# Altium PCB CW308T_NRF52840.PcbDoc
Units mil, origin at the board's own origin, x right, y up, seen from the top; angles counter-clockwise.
Board outline 2060 x 2540 mil, 2 copper layers (Top Layer, Bottom Layer); 28 components, 41 nets, 193 pads, 144 vias.
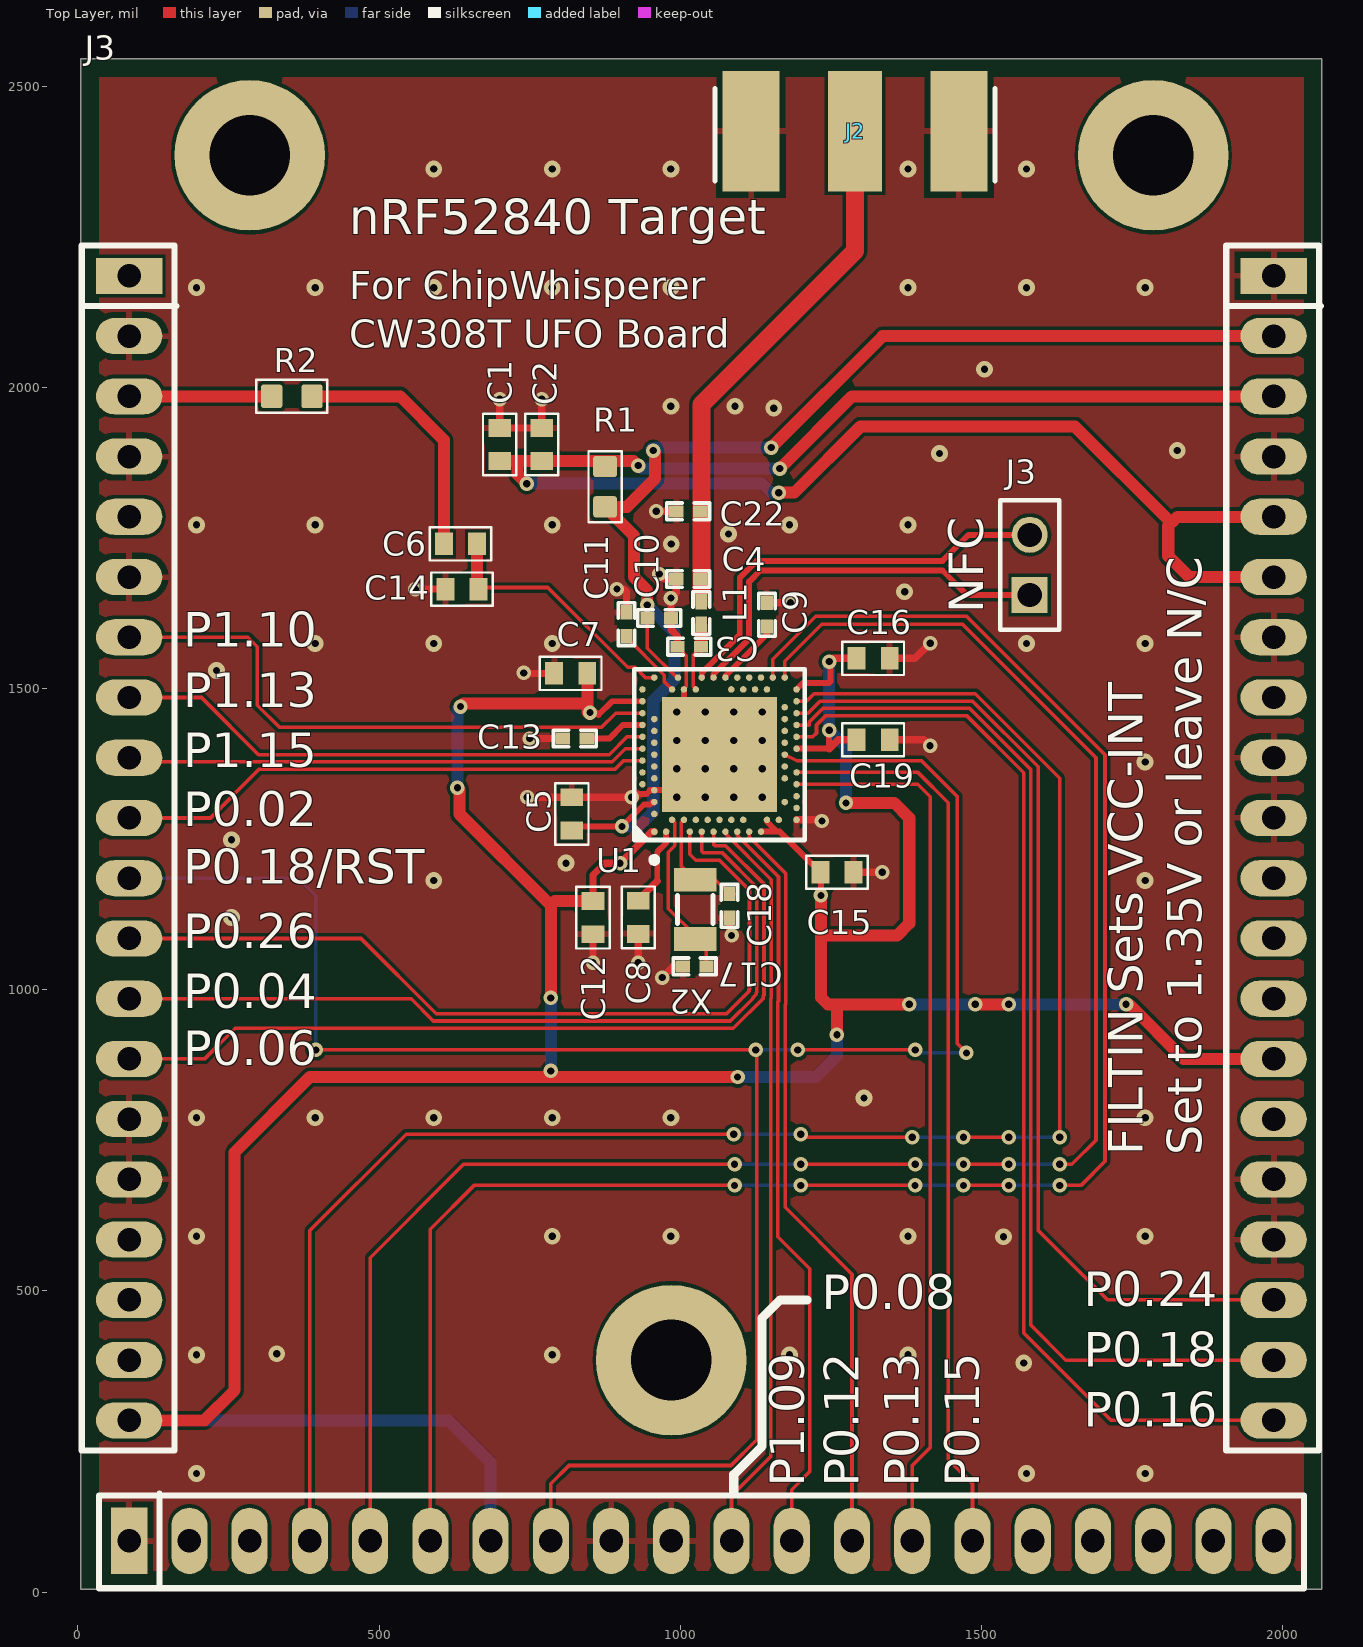
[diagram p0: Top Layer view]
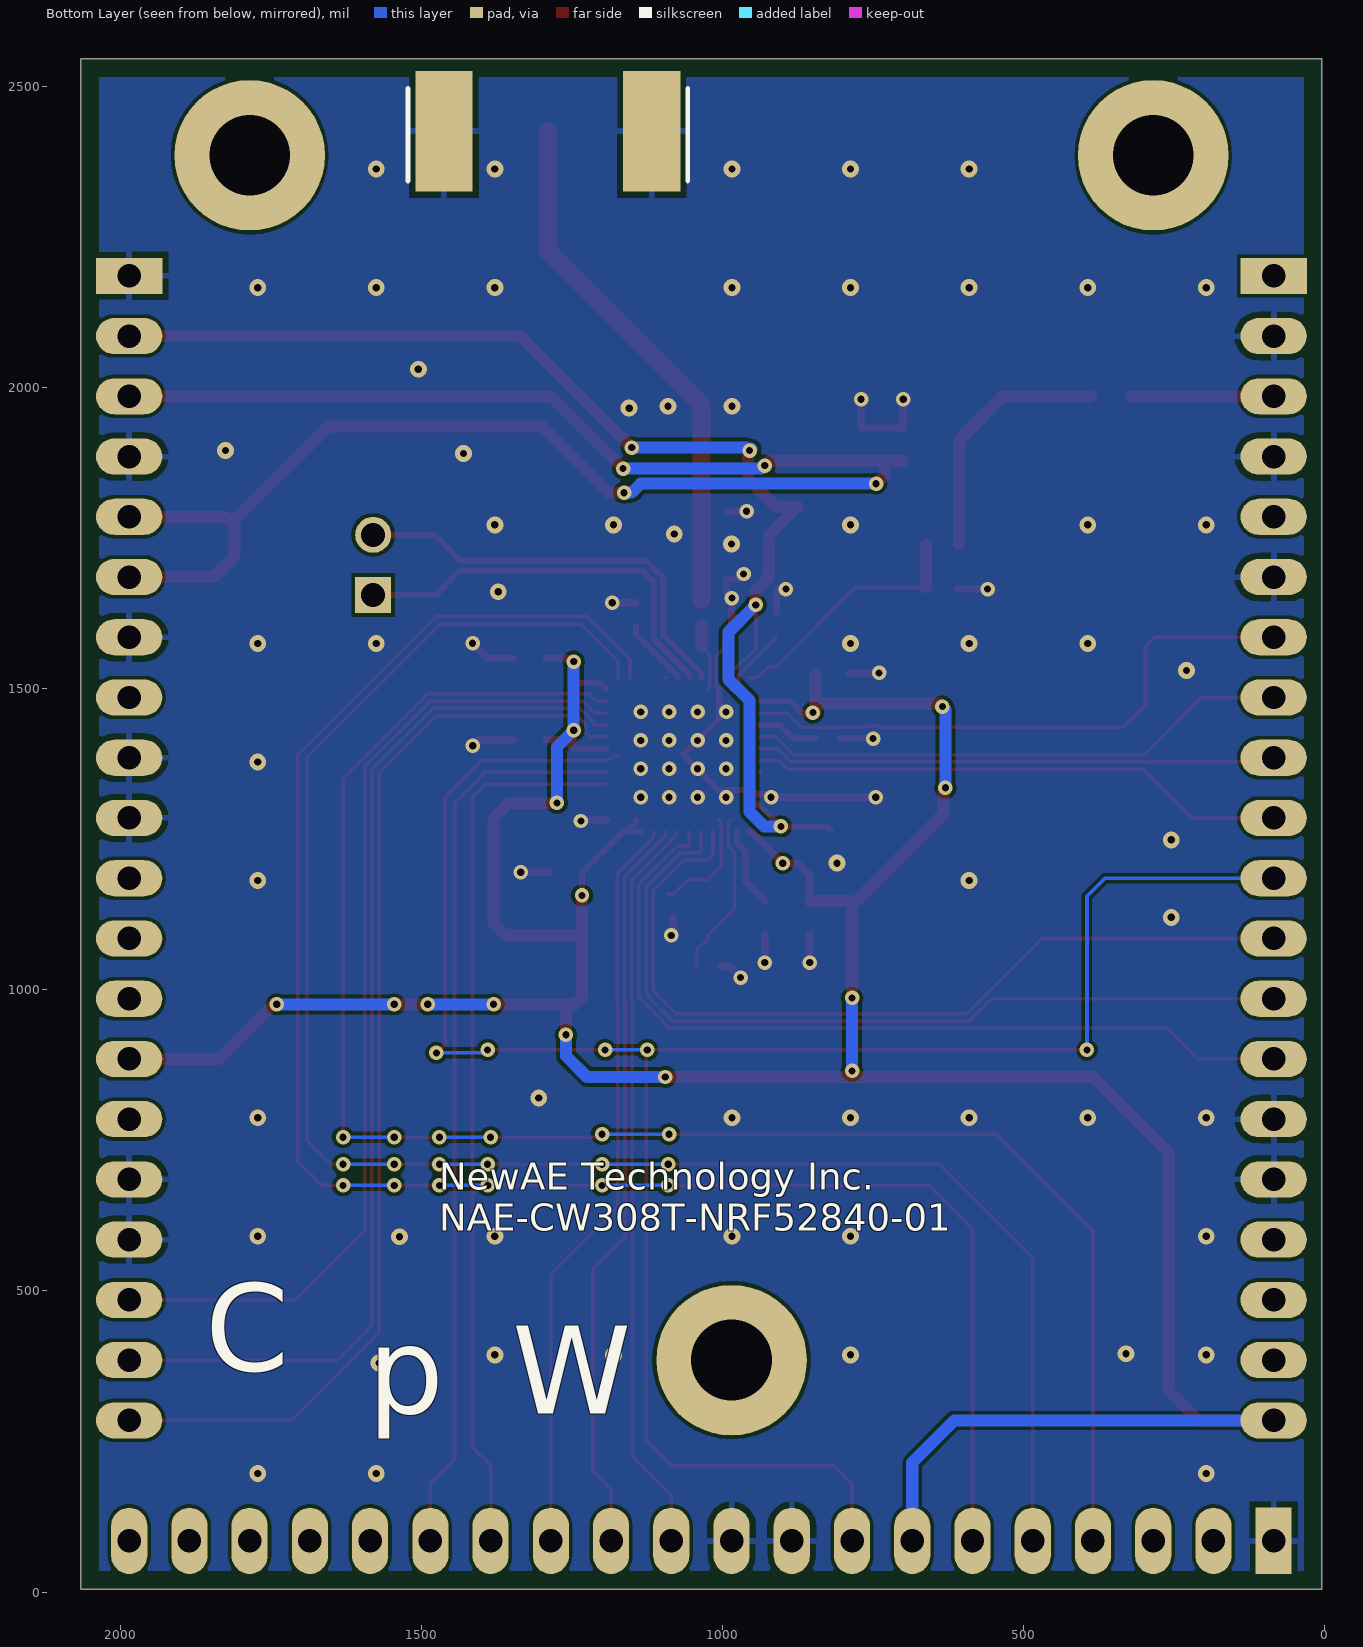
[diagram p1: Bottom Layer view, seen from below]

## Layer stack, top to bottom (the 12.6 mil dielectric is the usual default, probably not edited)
Top Solder: solder mask 0.4, Solder Resist, Dk 3.5
Top Layer: signal copper 1.4
Dielectric 1: dielectric 12.6, FR-4, Dk 4.8
Bottom Layer: signal copper 1.4
Bottom Solder: solder mask 0.4, Solder Resist, Dk 3.5

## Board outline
5,5 5,2545 2065,2545 2065,5

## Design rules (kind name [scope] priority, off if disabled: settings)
BoardOutlineClearance Silk_to_Outline [(OnLayer('Top Overlay'))] p1: gap=0 ignorepadtopadclearanceinfootprint=FALSE
BoardOutlineClearance [All] p2: gap=30 ignorepadtopadclearanceinfootprint=FALSE
Clearance [All] p1: gap=6 ignorepadtopadclearanceinfootprint=FALSE except(0: Arc-Hole Track-Hole SMDPad-Hole THPad-Hole Via-Hole Fill-Hole Poly-Hole Region-Hole Text-Hole)
HoleSize [All] p1: absolutevalues=TRUE maxlimit=200 minlimit=1 maxpercent=80.000 minpercent=20.000
MinimumSolderMaskSliver [All] p1: minsoldermaskwidth=5
PlaneConnect PlaneConnect_viaDirect [IsVia] p1: planeconnectstyle=Direct reliefexpansion=20 reliefentries=4 reliefconductorwidth=10 reliefairgap=10
PlaneConnect [All] p2: planeconnectstyle=Relief reliefexpansion=20 reliefentries=4 reliefconductorwidth=10 reliefairgap=10
PolygonConnect PolygonConnect_viaDirect [All vs isVia] p1: connectstyle=Direct reliefconductorwidth=10 reliefentries=4 polygonreliefangle="90 Angle" airgapwidth=10
PolygonConnect [All] p2: connectstyle=Relief reliefconductorwidth=10 reliefentries=4 polygonreliefangle="90 Angle" airgapwidth=10
RoutingVias [All] p1: holewidth=28 width=24 viastyle="Through Hole" minholewidth=12 minwidth=24 maxholewidth=12 maxwidth=50
SilkToSilkClearance [All] p1: silktosilkclearance=5
SilkToSolderMaskClearance [IsPad] p1: minsilkscreentomaskgap=5 clearancetoexposedcopper=TRUE
SolderMaskExpansion [All] p1: expansion=4
Width [All] p1: maxlimit=100 minlimit=6 preferedwidth=8 minimp=50.000000 maximp=50.000000 favimp=50.000000
25 further rules are at their usual default settings.

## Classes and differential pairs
component class NRF52840_UFO: J3

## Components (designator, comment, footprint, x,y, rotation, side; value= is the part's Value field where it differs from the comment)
C1 "2u2" CAPC0603_M 700,1905 r90 top
C2 "100n" CAPC0603_M 770,1905 r90 top
C3 "1.0pF" CAPC1005X04L 1014.79,1569.35 r0 top
C4 "1.0pF" CAPC1005X04L 1013,1681.75 r0 top
C5 "1u" CAPC0603_M 820,1291.73 r90 top
C6 "100p" CAPC0603_M 635,1740 r180 top
C7 "100n" CAPC0603_M 817.95,1525 r180 top
C8 "100n" CAPC0603_M 930,1120 r270 top
C9 "820pF" CAPC1005X04L 1143.74,1622.44 r90 top
C10 "N.C." CAPC1005X04L 965,1616.75 r180 top
C11 "100pF" CAPC1005X04L 910.47,1606.69 r90 top
C12 "1u" CAPC0603_M 855,1119.39 r270 top
C13 "N.C." CAPC1005X04L 824.84,1416.73 r180 top
C14 "100p" CAPC0603_M 637.56,1665 r180 top
C15 "2u2" CAPC0603_M 1260,1195 r0 top
C16 "100n" CAPC0603_M 1320,1550 r0 top
C17 "12pF" CAPC1005X04L 1023.66,1038.68 r180 top
C18 "12pF" CAPC1005X04L 1081.73,1139.08 r270 top
C19 "100n" CAPC0603_M 1320,1415 r0 top
C22 "N.C." CAPC1005X04L 1013,1794.05 r180 top
J2 "CON-SMA-PCBEDGE-003.062" CON-SMAM-PCB-EDGE062 1290,2425 r90 top
J3 "MTLW-102-05-L-S-172" SMTC-MTLW-102-05-X-S-172 1580,1655 r90 top
J3 "CW308_TARGETCON" CW308_TBOARD_CONN 85,2185 r0 top locked
L1 "3.9nH" INDC1005X04L 1034.79,1625.35 r90 top
R1 "12R" RESC1608X55N 875,1835 r270 top
R2 "12R" RESC1608X55N 355,1985 r180 top
U1 "nRF52840-QIAA" AQFN50P700X700X85_HS-74N 1065,1390.16 r90 top
X2 "32.768kHz" XTAL_3215 1024.65,1133.17 r90 top

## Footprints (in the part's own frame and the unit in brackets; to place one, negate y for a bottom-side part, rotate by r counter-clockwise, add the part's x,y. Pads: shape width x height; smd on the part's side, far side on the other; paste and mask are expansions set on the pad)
AQFN50P700X700X85_HS-74N [mm] "AQFN, 73-Leads, Body 7.00x7.00mm, Pitch 0.50mm, Thermal Pad 4.95x4.95mm, IPC Medium Density"
  rect 4.85x4.85 smd paste-0.711 mask+0.05: 74(0,0)
  round 0.275 smd paste+0.012 mask+0.05: A8(-1.25,3.25) A10(-0.75,3.25) A12(-0.25,3.25) A14(0.25,3.25) A16(0.75,3.25) A18(1.25,3.25) A20(1.75,3.25) A22(2.25,3.25) A23(2.75,3.25) AA24(3.25,-2.25) AB2(-2.75,-2.5) AC5(-2,-2.75) AC9(-1,-2.75) AC11(-0.5,-2.75) AC13(0,-2.75) AC15(0.5,-2.75) AC17(1,-2.75) AC19(1.5,-2.75) AC21(2,-2.75) AC24(3.25,-2.75) AD2(-2.75,-3.25) AD4(-2.25,-3.25) AD6(-1.75,-3.25) AD8(-1.25,-3.25) AD10(-0.75,-3.25) AD14(0.25,-3.25) AD16(0.75,-3.25) AD18(1.25,-3.25) AD20(1.75,-3.25) AD22(2.25,-3.25) AD23(2.75,-3.25) B1(-3.25,2.75) B3(-2.5,2.75) B5(-2,2.75) B7(-1.5,2.75) B9(-1,2.75) B11(-0.5,2.75) B13(0,2.75) B15(0.5,2.75) B17(1,2.75) B19(1.5,2.75) B24(3.25,2.75) C1(-3.25,2.25) D2(-2.75,2) D23(2.75,2) E24(3.25,1.75) F2(-2.75,1.5) F23(2.75,1.5) G1(-3.25,1.25) H2(-2.75,1) H23(2.75,1) J1(-3.25,0.75) J24(3.25,0.75) K2(-2.75,0.5) L1(-3.25,0.25) L24(3.25,0.25) M2(-2.75,0) N1(-3.25,-0.25) N24(3.25,-0.25) P2(-2.75,-0.5) P23(2.75,-0.5) R1(-3.25,-0.75) R24(3.25,-0.75) T2(-2.75,-1) T23(2.75,-1) U1(-3.25,-1.25) U24(3.25,-1.25) V23(2.75,-1.5) W1(-3.25,-1.75) W24(3.25,-1.75) Y2(-2.75,-2) Y23(2.75,-2)
  silkscreen extent -4.56,-3.6 3.6,3.6, body extent -3.55,-3.55 3.55,3.55, height 0.85
CAPC0603_M [mm]
  rect 0.75x0.95 smd: 1(-0.7,0) 2(0.7,0)
  silkscreen extent -1.3,-0.7 1.3,0.7, body extent -0.85,-0.45 0.85,0.45, height 0.9
CAPC1005X04L [mm] "Chip Capacitor, 2-Leads, Body 1.0x0.5mm, IPC High Density"
  rect 0.6x0.5 smd: 1(-0.5,0) 2(0.5,0)
  silkscreen extent -0.9,-0.35 0.9,0.35, body extent -0.51,-0.25 0.51,0.25, height 0.5
CON-SMAM-PCB-EDGE062 [mm] "Connector, SMA Edge Mount for 0.062\" Thick Board, 5-Lead"
  rect 5.08x2.29 smd paste-25.4: 1(0,0)
  rect 5.08x2.415 smd paste-25.4: 2(0,-4.383) 5(0,4.383)
  rect 5.08x2.415 smd far side paste-25.4: 3(0,-4.383) 4(0,4.383)
  silkscreen extent -2.1,-5.9 1.8,5.9, body extent -2.15,-4.8 15.3,4.72, height 4.34
CW308_TBOARD_CONN [mil]
  rect 110x60 hole 39: A1(0,0) C1(1900,0)
  oval 110x60 hole 39: A2(0,-100) A3(0,-200) A4(0,-300) A5(0,-400) A6(0,-500) A7(0,-600) A8(0,-700) A9(0,-800) A10(0,-900) A11(0,-1000) A12(0,-1100) A13(0,-1200) A14(0,-1300) A15(0,-1400) A16(0,-1500) A17(0,-1600) A18(0,-1700) A19(0,-1800) A20(0,-1900) C2(1900,-100) C3(1900,-200) C4(1900,-300) C5(1900,-400) C6(1900,-500) C7(1900,-600) C8(1900,-700) C9(1900,-800) C10(1900,-900) C11(1900,-1000) C12(1900,-1100) C13(1900,-1200) C14(1900,-1300) C15(1900,-1400) C16(1900,-1500) C17(1900,-1600) C18(1900,-1700) C19(1900,-1800) C20(1900,-1900)
  rect 60x110 hole 39: B1(0,-2100)
  oval 60x110 hole 39: B2(100,-2100) B3(200,-2100) B4(300,-2100) B5(400,-2100) B6(500,-2100) B7(600,-2100) B8(700,-2100) B9(800,-2100) B10(900,-2100) B11(1000,-2100) B12(1100,-2100) B13(1200,-2100) B14(1300,-2100) B15(1400,-2100) B16(1500,-2100) B17(1600,-2100) B18(1700,-2100) B19(1800,-2100) B20(1900,-2100)
  round 250 hole 134: MH1(200,200) MH2(900,-1800) MH2(1700,200)
  silkscreen extent -79,-2179 1979,50, body extent -50,-2149 1950,50, height 48
INDC1005X04L [mm] "Chip Inductor, 2-Leads, Body 1.0x0.5mm, IPC High Density"
  rect 0.65x0.5 smd: 1(-0.475,0) 2(0.475,0)
  silkscreen extent -0.9,-0.35 0.9,0.35, body extent -0.5,-0.3 0.5,0.3, height 0.5
RESC1608X55N [mm] "Chip Resistor, Body 1.6x0.8mm, EIA 0603, IPC Medium Density"
  round 0.254 on Mech15: 0(0,0)
  rrect25% 0.9x1 smd: 1(-0.85,0) 2(0.85,0)
  Top Layer pour cut-out: -0.6,0.5 0.6,0.5 0.6,-0.5 -0.6,-0.5
  silkscreen extent -1.5,-0.7 1.5,0.7, body extent -0.87,-0.47 0.88,0.48, height 0.54
SMTC-MTLW-102-05-X-S-172 [mm] "Terminal Assembly, 1x2 Pins, Vertical, 2.54mm Pitch, Male"
  rect 1.52x1.52 hole 1.02: 1(0,0)
  round 1.52 hole 1.02: 2(2.54,0)
  silkscreen extent -1.46,-1.24 4,1.24, body extent -1.27,-1.24 3.81,1.24, height 5.89
XTAL_3215 [mm] "XTAL SMD 3.2 x 1.5 mm"
  rect 1x1.8 smd: 1(-1.25,0) 2(1.25,0)
  silkscreen extent -0.6,-0.75 0.6,0.75, body extent -1.6,-0.75 1.6,0.75, height 0.81

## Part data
C1 C15: library part CCHIP-2u2-0603, "2u2, 0603", Case-EIA=0603, Case-Metric=1608, Manufacture 1=Samsung, Manufacture Part Number 1=CL10B225KP8NNNC, Rated Voltage=10VDC, Supplier Part Number 1=1276-1134-2-ND
C2 C7 C8 C16 C19: library part CCHIP-100n-0603, "100n, 0603", Case-EIA=0603, Case-Metric=1608, Manufacture 1=Kemet, Manufacture Part Number 1=C0603C104K5RACTU, Rated Voltage=50VDC, Supplier Part Number 1=399-5089-2-ND
C3 C4: library part C0402-1.0p, "Capacitor, NP0, ±5%"
C5 C12: library part CCHIP-1u-0603, "1u, 0603, 50V", Case-EIA=0603, Case-Metric=1608, Manufacture Part Number 1=CL10A105KB8NNNC, Rated Voltage=50VDC, Supplier Part Number 1=1276-1860-1-ND
C6 C14: library part CCHIP-100p-0603, "100p, 0603", Case-EIA=0603, Case-Metric=1608, Manufacture 1=KEMET, Manufacture Part Number 1=C0603C101K5RACTU, Rated Voltage=50V, Supplier Part Number 1=399-7824-1-ND
C9: library part C0402-820p, "Capacitor, NP0, ±5%"
C10 C13 C22: library part C0402-N.C., "Not mounted"
C11: library part C0402-100p, "Capacitor, NP0, ±5%"
C17 C18: library part C0402-12p, "Capacitor, NP0, ±2%"
J2: "SMA Female Edge Mount Connector for 0.062\" Thick Board"
J3: library part CMP-1024-00067-1, Manufacturer=Samtec, Temperature Range="-55 to 125 degC"
J3: library part CW308_TBOARD, "CW308 \"Standard\" Target Board Connector"
L1: library part L0402-3n9, "High frequency chip inductor ±5%"
R1 R2: library part RCHIP-12R-0603, "12R res, 0603, 1%, 1/10W", Case-EIA=0603, Case-Metric=1608, Manufacture 1=Yageo, Manufacture Part Number 1=RC0603FR-0712RL, Rated Power=0.1W, Rated Voltage=75VDC, Supplier Part Number 1=311-12.0HRCT-ND, Temperature Range="-55C to 155C", Tolerance=1%
U1: library part nRF52840-QIAAC0, "Multi-protocol Bluetooth Low Energy, IEEE 802.15.4, ANT and 2.4GHz proprietary system-on-chip", Manufacturer="Nordic Semiconductor"
X2: library part XTAL_SMD3215_32.768kHz_9pF_General, "XTAL SMD 3215, 32.768kHz, Cl=9pF, Total Tol: ±50ppm"

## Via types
v1: diameter 24, hole 12, Top Layer to Bottom Layer, tented both sides, 83 vias
v2: diameter 28, hole 12, Top Layer to Bottom Layer, tented both sides, 61 vias

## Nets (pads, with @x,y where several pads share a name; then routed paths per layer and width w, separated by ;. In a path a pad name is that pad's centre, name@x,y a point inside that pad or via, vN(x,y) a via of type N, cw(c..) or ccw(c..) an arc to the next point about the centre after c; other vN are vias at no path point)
CLKIN: J3.A3 R2.2 | length 236.5
  Top Layer w20: J3.A3 R2.2
DEC1: C8.1 U1.C1 | length 133.9
  Top Layer w9.84: 961.65,1180.51 961.65,1228.74 976.42,1243.5 U1.C1
  Top Layer w12: C8.1 930,1148.86 961.65,1180.51
DEC3: C11.1 U1.D23 | length 118
  Top Layer w5.91: C11.1@910.47,1585.04 973.46,1522.05 973.46,1511.44 986.26,1498.64 U1.D23
GND: C1.2 C2.2 C3.1 C4.1 C5.2 C7.2 C8.2 C9.2 C10.1 C11.2 C12.2 C13.2 C14.2 C15.2 C16.2 C17.2 C18.2 C19.2 C22.2 J2.2 J2.3 J2.4 J2.5 J3.A2 J3.A4 J3.A6 J3.A15 J3.A16 J3.B1 J3.B9 J3.B10 J3.C1 J3.C4 J3.C7 J3.C9 J3.C10 J3.C16 J3.C17 U1.74 U1.AD2 U1.B7 U1.F23 | length 1559
  Top Layer w5.71: C3.1 1010.08,1554.38 1010.08,1502.56 U1.F23
  Top Layer w9.84: v1@921.59,1324.9 943.69,1324.9 949.89,1331.1 U1.B7 1005.94,1331.1 U1.74 1005.94,1449.21 U1.F23
  Top Layer w12: v1(560,1665) C14.2 ; v1(700,1980) C1.2 C2.2 v1(770,1980) ; v1(740,1525.73) 740.73,1525 C7.2 ; v1(745.71,1319.29) C5.2 v1(919.33,1319.29) ; v1(750,1416.73) C13.2 ; v1(855,1045) C12.2 ; v1(894.69,1665) 906.06,1665 910.47,1660.59 C11.2 ; v1(930,1045) C8.2 ; v1(960,1794.05) C22.2 ; v1(965,1690) 973.25,1681.75 C4.1 993.32,1658.94 v1(984.37,1650) 984.68,1649.69 C10.1 984.68,1597.52 995.1,1587.11 C3.1 ; v1(970,1020) 988.68,1038.68 C17.2 ; C18.2 1081.73,1093.23 v1(1085,1089.96) ; C9.2 v1(1182.88,1642.12) ; U1.AD2 1233.11,1281.89 v1(1235,1280) ; C15.2 v1(1335,1195) ; C19.2 1404.66,1415 v1(1414.66,1405) ; C16.2 1389.66,1550 1414.66,1575 v1(1415,1575)
  other v1: 994.13,1319.29 1041.38,1319.29 1088.62,1319.29 1135.87,1319.29 994.13,1366.54 1041.38,1366.54 1088.62,1366.54 1135.87,1366.54 994.13,1413.78 1041.38,1413.78 1088.62,1413.78 1135.87,1413.78 994.13,1461.02 1041.38,1461.02 1088.62,1461.02 1135.87,1461.02
  other v2: 196.85,196.85 1574.8,196.85 1771.65,196.85 1570,380 196.85,393.7 787.4,393.7 1181.1,393.7 1377.95,393.7 330,395.44 1536.42,589.87 196.85,590.55 787.4,590.55 984.25,590.55 1377.95,590.55 1771.65,590.55 196.85,787.4 393.7,787.4 590.55,787.4 787.4,787.4 984.25,787.4 1771.65,787.4 1305,819.94 255,1120.07 590.55,1181.1 1771.65,1181.1 810,1210 255,1248.69 1771.65,1377.95 229.77,1529.65 393.7,1574.8 590.55,1574.8 787.4,1574.8 1574.8,1574.8 1771.65,1574.8 1372.4,1660.59 985,1739.79 1080.04,1756.47 196.85,1771.65 393.7,1771.65 787.4,1771.65 1181.1,1771.65 1377.95,1771.65 1430,1890 1825,1895 1155,1965.31 984.25,1968.5 1090.59,1968.5 1505,2030 196.85,2165.35 393.7,2165.35 590.55,2165.35 787.4,2165.35 984.25,2165.35 1377.95,2165.35 1574.8,2165.35 1771.65,2165.35 590.55,2362.2 787.4,2362.2 984.25,2362.2 1377.95,2362.2 1574.8,2362.2
GPIO1_TX: J3.A7 U1.A20 | length 982.3
  Top Layer w6: J3.A7 282.01,1585 297.85,1569.16 297.85,1472.15 334.43,1435.57 739.14,1435.57 741.3,1437.73 758.7,1437.73 760.86,1435.57 869.11,1435.57 892.59,1459.06 U1.A20
GPIO2_RX: J3.A8 U1.A16 | length 903.6
  Top Layer w6: J3.A8 205,1485 299.84,1390.16 881.96,1390.16 911.49,1419.68 U1.A16
GPIO3: J3.A9 U1.A14 | length 863.9
  Top Layer w6: J3.A9 91.84,1378.16 886.93,1378.16 908.77,1400 U1.A14
GPIO4: J3.A10 U1.A12 | length 891.5
  Top Layer w6: J3.A10 220,1285 301.16,1366.16 891.9,1366.16 906.06,1380.31 U1.A12
HDR1: J3.B11 U1.N1 | length 1236
  Top Layer w6: U1.N1 1074.84,1258.62 1150.86,1182.6 1150.86,985.54 1149.9,984.58 1149.9,224.9 1085,160 J3.B11
HDR2: J3.B12 U1.R1 | length 1240.3
  Top Layer w6: U1.R1 1094.53,1255.91 1162.86,1187.58 1162.86,980.57 1161.9,979.61 1161.9,589.87 1215,536.77 1215,200 1185,170 J3.B12
HDR3: J3.B13 U1.U1 | length 1248.7
  Top Layer w6: U1.U1 1114.21,1253.35 1174.86,1192.7 1174.86,975.6 1173.9,974.64 1173.9,638.7 1285,527.6 J3.B13
HDR4: J3.B14 U1.AD8 | length 1478.1
  Top Layer w5.91: U1.AD8 1345,1340.94
  Top Layer w6: 1345,1340.94 1394.06,1340.94 1415,1320 1415,240 1385,210 J3.B14
HDR5: J3.B15 U1.AD10 | length 1514.6
  Top Layer w5.91: U1.AD10 1394.37,1360.63
  Top Layer w6: 1394.37,1360.63 1444.92,1310.08 1444.92,220.08 1485,180 J3.B15
HDR6: J3.B16
HDR7: J3.B17
HDR8: J3.B18
HDR9: J3.B19
HDR10: J3.B20
LED1: J3.C18 U1.AD20 | length 1663.1
  Top Layer w6: U1.AD20 1211.99,1459.06 1231.94,1479 1484.94,1479 1594,1369.94 1594,600 1709,485 J3.C18
LED2: J3.C19 U1.AD18 | length 1794.8
  Top Layer w6: U1.AD18 1193.11,1439.21 1214.09,1439.21 1214.09,1444.18 1236.91,1467 1479.97,1467 1582,1364.97 1582,443 1640,385 J3.C19
LED3: J3.C20 U1.AD16 | length 1843.8
  Top Layer w6: U1.AD16 1219.68,1419.68 1226.09,1426.09 1226.09,1439.21 1241.88,1455 1475,1455 1570,1360 1570,430 1715,285 J3.C20
MISO: J3.A13 U1.J1 | length 1402.3
  Top Layer w6: J3.A13 553.03,985 590.03,948 1083,948 1120,985 1120,986.26 1125.9,992.16 1125.9,994.52 1126.86,995.48 1126.86,1170.14 1070,1227 1038,1227 1035.47,1229.53 U1.J1
MOSI: J3.A14 U1.L1 | length 1416.6
  Top Layer w6: J3.A14 210,885 261,936 1087.97,936 1137.9,985.93 1137.9,989.55 1138.86,990.51 1138.86,1175.25 1075.11,1239 1057.03,1239 1055.16,1240.87 U1.L1
NetC3_2: C3.2 L1.1 U1.H23 | length 113.7
  Top Layer w5.71: U1.H23 1021.5,1502.56 1021.5,1556.31 1034.66,1569.47 C3.2@1034.86,1569.67
  Top Layer w20: C3.2@1034.66,1569.47 L1.1@1034.66,1604.67
NetC6_1: C6.1 C14.1 U1.B24 | length 428.5
  Top Layer w6: C14.1@662.56,1667.56 780,1667.56 912.56,1535 925.01,1535 941.9,1518.11 U1.B24
  Top Layer w20: C14.1@662.56,1667.56 C6.1
NetC6_2: C6.2 R2.1 | length 421.5
  Top Layer w20: R2.1 535,1985 607.44,1912.56 C6.2
NetC9_1: C9.1 U1.N24 | length 113.2
  Top Layer w9.84: U1.N24 1074.84,1521.11 1143.74,1590.01 C9.1
NetC13_1: C13.1 U1.A18 | length 101.9
  Top Layer w9.84: C13.1 881.96,1416.73 904.6,1439.37 U1.A18
NFC1: J3.1 U1.L24 | length 674.2
  Top Layer w9.84: U1.L24 1055.16,1523.42 1114.21,1582.48 1114.21,1677.37 1133,1696.16 1435,1696.16 ; 1435,1695.87 1435.29,1695.87 1476.16,1655 J3.1
NFC2: J3.2 U1.J24 | length 702.6
  Top Layer w9.84: U1.J24 1035.47,1525.73 1098.66,1588.92 1098.66,1683.81 1126.56,1711.71 1435,1711.71 ; 1435,1712 1435.29,1712 1478.29,1755 J3.2
NRST: J3.A11 J3.B8 U1.AC13 | length 3519.6
  Top Layer w6: v1(395,900) v1(1125,900) 1126.86,898.14 1126.86,252.8 1084.06,210 815.16,210 785,179.84 J3.B8 ; U1.AC13 1192.95,1380.31 1399.69,1380.31 1460,1320 1460,910 v1(1475,895) ; v1(1195,900) v1(1390,900)
  Bottom Layer w6: J3.A11 365,1185 395,1155 v1(395,900) ; v1(1125,900) v1(1195,900) ; v1(1390,900) 1395,895 v1(1475,895)
P0.00/XL1: C17.1 U1.D2 X2.1 | length 275.4
  Top Layer w5.71: U1.D2 990.39,1277.76 990.39,1238.78 989.9,1238.29 989.9,1237.92 980.06,1228.08 980.06,1134.55 1024.65,1089.96 X2.1 1043.35,1065.26 C17.1
P0.01/XL2: C18.1 U1.F2 X2.2 | length 186.4
  Top Layer w5.71: U1.F2 1001.81,1277.76 1001.81,1205.22 X2.2 1058.11,1182.39 C18.1
  Top Layer w5.91: C18.1 C18.1@1090.59,1158.76
RF: C4.2 C22.1 J2.1 L1.2 | length 883.9
  Top Layer w30: L1.2@1035,1646.75 1035,1971.57 1290,2226.57 J2.1
SCK: J3.A12 U1.G1 | length 1425.5
  Top Layer w6: J3.A12 470,1085 595,960 1076.77,960 1113.9,997.13 1113.9,999.49 1114.86,1000.45 1114.86,1165.14 1065,1215 1025.79,1215 1015.79,1225 U1.G1
SHUNTH: C1.1 C2.1 J3.C3 J3.C5 J3.C6 R1.1 | length 2993.7
  Top Layer w20: C1.1 730,1877.44 ; v1(745,1840) 730,1855 730,1877.44 ; v1(930,1870) 922.56,1877.44 C2.1 730,1877.44 ; v1(1163.43,1825) 1189.09,1825 1299.09,1935 1655,1935 1812.5,1777.5 1817.5,1777.5 ; v1(1165,1865) 1285,1985 J3.C3 ; J3.C6 1845,1685 1810,1720 1810,1770 1817.5,1777.5 ; J3.C5 1825,1785 1817.5,1777.5
  Bottom Layer w20: v1(745,1840) 1135.87,1840 1150.87,1825 v1(1163.43,1825) ; v1(930,1870) 935,1865 v1(1165,1865)
SHUNTL: C5.1 C10.2 J3.C2 R1.2 U1.B5 U1.E24 | length 2193.3
  Top Layer w5.91: v1(944.92,1638.75) 944.92,1567.02 993.83,1518.11 U1.E24
  Top Layer w9.84: C5.1 826.89,1271.06 v1(903.11,1271.06) 939.52,1307.48 949.79,1307.48 953.73,1311.42 U1.B5
  Top Layer w20: v1(944.92,1638.75) 944.92,1662.91 923,1684.83 923,1753.54 R1.2 911.33,1801.54 958,1848.21 958,1892 v1(955,1895) ; v1(1150.86,1900) 1335.86,2085 J3.C2
  Bottom Layer w20: v1(903.11,1271.06) 931.06,1271.06 955,1295 955,1480 990,1515 990,1593.67 v1(944.92,1638.75) ; v1@952,1898 v1(955,1895) 960,1900 v1(1150.86,1900)
SWDCLK: J3.B6 U1.AA24 | length 3070.8
  Top Layer w6: J3.B6 585,602.44 657.56,675 v1(1090,675) ; U1.AA24 1153.58,1548.58 1225,1620 1475,1620 1705,1390 1705,715 1665,675 v1(1630,675) ; v1(1200,675) v1(1389.66,675) ; v1(1470,675) v1(1545,675)
  Bottom Layer w6: v1(1090,675) v1(1200,675) ; v1(1389.66,675) v1(1470,675) v1@1475,675 ; v1(1545,675) v1(1630,675)
SWDIO: J3.B5 U1.AC24 | length 3056.7
  Top Layer w6: J3.B5 485,555 640,710 v1(1090,710) ; U1.AC24 1173.27,1545 1234.92,1606.65 1468.35,1606.65 1690,1385 1690,750 1650,710 v1(1630,710) ; v1@1195,710 v1(1200,710) v1(1390,710) ; v1(1470,710) v1(1545,710)
  Bottom Layer w6: v1(1090,710) v1(1200,710) ; v1(1390,710) v1(1470,710) ; v1(1545,710) v1(1630,710)
SWO: J3.B4 U1.AD22 | length 2929.8
  Top Layer w6: J3.B4 385,600 545,760 v1(1088.62,760) ; U1.AD22 1209.26,1478.74 1221.99,1491.47 1489.45,1491.47 1630,1350.91 v1(1630,755) ; v1(1200,760) 1205,755 v1(1385,755) ; v1@1465,755 v1(1470,755) v1(1545,755)
  Bottom Layer w6: v1(1088.62,760) v1(1200,760) ; v1(1385,755) v1(1470,755) ; v1(1545,755) v1(1630,755)
VCC: C7.1 C12.1 C15.1 C16.1 C19.1 J3.A20 J3.B7 J3.C14 U1.A22 U1.AD14 U1.AD23 U1.B1 U1.W1 U1.Y2 | length 5925.3
  Top Layer w9.84: v1(850,1460) 860.31,1460 864.21,1456.1 886.85,1478.74 U1.A22 ; U1.W1 1160.42,1262.2 ; U1.Y2 1143.74,1278.89 1160.42,1262.2 ; U1.AD14 1247.09,1400 v1(1247.09,1430.51) ; U1.AD23 1203.78,1509.25 1247.09,1509.25 1249.06,1511.22 v1@1249.06,1544.68 ; v1(1233.31,1156.48) 1233.31,1193.88 1164.98,1262.2 1160.42,1262.2
  Top Layer w12: C12.1 855,1190.22 874.78,1210 v1(900,1210) 952.2,1262.2 U1.B1 ; 1247.09,1400 1262.09,1415 C19.1 ; v1(1247.09,1544.68) 1252.4,1550 C16.1
  Top Layer w20: J3.A20 210,285 260,335 260,730 385,855 v1(1095,855) ; v1(630,1335) 633.27,1331.73 633.27,1291.73 785,1140 ; v1(635,1470) 640,1475 845.51,1475 ; v1(785,986.26) 785,1140 ; C7.1 845.51,1475 ; v1(850,1460) 846.54,1460 845.51,1461.02 845.51,1475 ; C12.1 791.95,1146.95 785,1140 ; v1(1233.31,1156.48) 1233.31,1089.96 ; v1(1260,925) 1260,975.6 ; v1(1275,1310) 1355,1310 1380,1285 1380,1110 1359.96,1089.96 1233.31,1089.96 ; v1(1380,975.6) 1260,975.6 ; v1(1489.45,975.6) v1(1545,975.6) ; v1(1740,975.6) 1745,975.6 1835.6,885 J3.C14 ; 1233.31,1089.96 1233.31,987.26 1244.97,975.6 1260,975.6
  Bottom Layer w20: J3.A20 615,285 685,215 J3.B7 ; v1(630,1335) 630,1465 v1(635,1470) ; v1(785,865) v1(785,986.26) ; v1(1095,855) 1225,855 1260,890 v1(1260,925) ; v1(1247.09,1544.68) v1(1247.09,1430.51) 1275,1402.6 v1(1275,1310) ; v1(1380,975.6) v1(1489.45,975.6) ; v1(1545,975.6) v1(1740,975.6)
pads on no net: J3.A1 J3.A5 J3.A17 J3.A18 J3.A19 J3.B2 J3.B3 J3.C8 J3.C11 J3.C12 J3.C13 J3.C15 J3.MH1 J3.MH2 R1.0 R2.0 U1.A8 U1.A10 U1.A23 U1.AB2 U1.AC5 U1.AC9 U1.AC11 U1.AC15 U1.AC17 U1.AC19 U1.AC21 U1.AD4 U1.AD6 U1.B3 U1.B9 U1.B11 U1.B13 U1.B15 U1.B17 U1.B19 U1.H2 U1.K2 U1.M2 U1.P2 U1.P23 U1.R24 U1.T2 U1.T23 U1.U24 U1.V23 U1.W24 U1.Y23
copper on no net: | length 2.7
  Top Layer w5.91: 935.67,1359.25 937.05,1360.63 ; 1094.53,1518.11 1094.53,1518.85

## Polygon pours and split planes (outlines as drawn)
GND on Bottom Layer "GND" (solid, remove dead copper, pour order 0): 0,2650 5,2645 2220,2645 2220,15 2205,0 0,0
GND on Top Layer "GND" (solid, remove dead copper, pour order 2): 0,2660 55,2715 2280,2715 2280,20 2260,0 0,0

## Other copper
Top Layer:
  pour cut-out: 1094.53,1400 1035.47,1400 1035.47,1498.43 1094.53,1498.43
  pour cut-out: 1077.79,1521.35 1077.79,1629.33 1004.96,1629.33 1004.96,1597.83 963.79,1597.83 963.79,1521.35

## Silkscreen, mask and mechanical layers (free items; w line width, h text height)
Top Overlay:
  lines w15: 1088.62,163.74 1088.62,194.88 1135.87,242.13 1135.87,455 1165.87,485 1210,485
  text "nRF52840 Target" at 450,2235 h100
  text "For ChipWhisperer / CW308T UFO Board" at 450,2050 h80
  text "NFC" at 1522.28,1625 h98.43 r90
  text "P1.10" at 175,1550 h98.43
  text "P1.13" at 175,1450 h98.43
  text "P1.15" at 175,1350 h98.43
  text "P0.02" at 175,1252.36 h98.43
  text "P0.18/RST" at 175,1156.8 h98.43
  text "P0.26" at 175,1050 h98.43
  text "P0.04" at 175,950 h98.43
  text "P0.06" at 175,855 h98.43
  text "FILTIN Sets VCC-INT / Set to 1.35V or leave N/C" at 1885,725 h98.43 r90
  text "P0.24" at 1670,455 h98.43
  text "P0.08" at 1235,450 h98.43
  text "P0.18" at 1670,355 h98.43
  text "P0.16" at 1670,255 h98.43
  text "P1.09" at 1225,175 h98.43 r90
  text "P0.12" at 1315,175 h98.43 r90
  text "P0.13" at 1415,175 h98.43 r90
  text "P0.15" at 1515,175 h98.43 r90
Bottom Overlay:
  text "NewAE Technology Inc. / NAE-CW308T-NRF52840-01" at 1470,600 h45
  text "C" at 1859,318 h250
  text "W" at 1349,248 h250
  text "p" at 1589,248 h250
Mechanical 1:
  the board outline again, w10

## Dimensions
2065,2545 to 2065,5 on Drill Guide
5,2545 to 2065,2545 on Drill Guide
